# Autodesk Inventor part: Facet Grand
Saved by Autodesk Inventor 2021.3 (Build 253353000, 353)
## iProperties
Created: 2022-09
Part Number: Facet Grand
Material: Generic
Document SubType Name: Modeling
Designer: Administrator
Density: 1 g/cm^3
Appearance: Default
Title: Facet Grand
Author: Administrator
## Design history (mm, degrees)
feature "Glass-Facet Grand"
body "Solid1"
